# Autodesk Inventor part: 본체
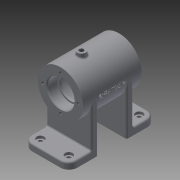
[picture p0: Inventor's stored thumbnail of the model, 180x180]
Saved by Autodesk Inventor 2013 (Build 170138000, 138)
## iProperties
Created: 2017-02
Part Number: 본체
Material: 일반
Document SubType Name: Modeling
Designer: Administrator
Density: 1 g/cm^3
Mass: 130.971 g
Surface Area: 425.852 cm^2
Volume: 130.971 cm^3
Author: Administrator
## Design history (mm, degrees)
sketch "스케치1"
  geometry: C1 r 27 at (0, 0); 1 further point
  constraints: 1 centre point, 1 coincident
  dimensions: "d0" = 54 diameter of C1
extrude "돌출1" new body sketch "스케치1" stored distance "d2" = 70; taper "d3" = 0 deg
sketch "스케치2"
  geometry: L1 (-35, 27)-(-35, -27) reference; L2 (35, -27)-(35, 27) reference; L3 (-35, 0)-(35, 0); L4 (-35, 0)-(-23, 0); L5 (-23, 0)-(-23, 16); L6 (-23, 16)-(-35, 16); L7 (-35, 16)-(-35, 0); L8 (-23, 0)-(-20, 0); L9 (-20, 0)-(-20, 14); L10 (-20, 14)-(-23, 14); L11 (-23, 14)-(-23, 0); L12 (-20, 0)-(20, 0); L13 (20, 0)-(20, 22); L14 (20, 22)-(-20, 22); L15 (-20, 22)-(-20, 0); L16 (0, 0)-(0, -10.976); L17 (20, 0)-(20, 14); L18 (23, 0)-(20, 0); L19 (20, 14)-(23, 14); L20 (23, 0)-(23, 16); L21 (23, 14)-(23, 0); L22 (35, 0)-(23, 0); L23 (35, 16)-(35, 0); L24 (23, 16)-(35, 16)
  constraints: 44 end point, 7 parallel, 5 symmetric about line, 3 horizontal, 3 perpendicular, 2 midpoint
  dimensions: "d4" = 12 distance of L5.end L6.end; "d6" = 3 distance of L9.end L10.end; "d7" = 40 distance of L13.end L14.end; "d8" = 32 diameter of L6 L4; "d9" = 28 diameter of L10 L3; "d10" = 44 diameter of L14 L3
revolve "회전1" sketch "스케치2" stored, may be unused: angle "d11" = 90 deg
node "작업 평면1"
sketch "스케치3"
  geometry: L1 (-27, -35)-(27, -35) reference; L2 (0, -35)-(0, -10); C1 r 5 at (0, -10); 1 further point
  constraints: 2 end point, 1 centre point, 1 coincident, 1 midpoint, 1 perpendicular
  dimensions: "d13" = 25 distance of L2.start L2.end; "d14" = 10 diameter of C1
extrude "돌출2" join sketch "스케치3" stored distance "d15" = 70; taper "d16" = 0 deg
hole "구멍1" diameter "d19" = 5.188; stored, may be unused: countersink angle "d23" = 90 deg, drill point angle "d25" = 118 deg; dims "d20" = 6, "d21" = 4, "d22" = 2, "d24" = 8, "d26" = 10, "d27" = 10
sketch "스케치4"
  geometry: L1 (0, 0)-(0, 21); C1 r 27 at (0, 0) reference; 1 further point
  constraints: 2 end point, 1 coincident, 1 vertical
  dimensions: "d28" = 21 distance of L1.start L1.end
hole "구멍2" sketch "스케치4" at (0, 21) diameter "d29" = 3.242; stored, may be unused: countersink angle "d33" = 90 deg, drill point angle "d35" = 118 deg; dims "d30" = 8, "d31" = 4, "d32" = 2, "d34" = 10
fillet "모깎기1" dims "d39" = 0.3, "d40" = 2
node "작업 평면3"
sketch "스케치5"
  geometry: L1 (-27, -52)-(27, -52); L2 (27, -52)-(27, -60); L3 (27, -60)-(-27, -60); L4 (-27, -60)-(-27, -52); L5 (0, -52)-(0, -60); 2 further points
  constraints: 10 end point, 3 midpoint, 2 parallel, 2 perpendicular, 1 horizontal, 1 vertical alignment
  dimensions: "d43" = 54 distance of L2.end L3.end; "d46" = 8 distance of L1.end L2.end; "d47" = 60 distance from line of L3 point (0, 0)
extrude "돌출3" join sketch "스케치5" distance "d48" = 35; taper "d49" = 0 deg
sketch "스케치6"
  geometry: L1 (54, 0)-(54, -35) reference; L2 (0, 0)-(54, 0); L3 (54, 0)-(54, -8); L4 (54, -8)-(0, -8); L5 (0, -8)-(0, 0); 1 further point
  constraints: 8 end point, 2 parallel, 1 horizontal, 1 perpendicular, 1 point on line
  dimensions: "d50" = 8 distance of L2.end L3.end
extrude "돌출4" join sketch "스케치6" stored distance "d52" = 35; taper "d53" = 0 deg
fillet "모깎기2" dims "d54" = 10
hole "구멍3" diameter "d57" = 5; stored, may be unused: countersink angle "d61" = 90 deg, drill point angle "d63" = 118 deg; dims "d55" = 10, "d56" = 10, "d58" = 8, "d59" = 9, "d60" = 3, "d62" = 10
fillet "모깎기3" dims "d67" = 2
fillet "모깎기4" dims "d68" = 2
sketch "스케치7"
  geometry: L1 (0, 0)-(16.339, -25.16); L2 (0, 0)-(0, -13.074)
  constraints: 4 end point, 1 vertical
  dimensions: "d69" = 33 deg angle of L1 L2; "d70" = 30 distance of L1.start L1.end
node "작업 평면4"
sketch "스케치8"
  geometry: C1 r 6 at (0, 0); 2 further points
  constraints: 1 centre point, 1 coincident
  dimensions: "d71" = 12 diameter of C1
extrude "돌출5" join sketch "스케치8" stored distance "d72" = 35; taper "d73" = 0 deg
hole "구멍4" diameter "d76" = 5.188; stored, may be unused: countersink angle "d80" = 90 deg, drill point angle "d82" = 118 deg; dims "d74" = 10, "d75" = 10, "d77" = 8, "d78" = 9, "d79" = 3, "d81" = 10
node "작업 평면5"
sketch "스케치9"
  geometry: L1 (0, 5.847)-(0, -5.847); L2 (-14.782, 0)-(14.782, 0); L3 (-14.782, 5.847)-(14.782, 5.847); L4 (14.782, 5.847)-(14.782, -5.847); L5 (14.782, -5.847)-(-14.782, -5.847); L6 (-14.782, -5.847)-(-14.782, 5.847); 2 further points
  constraints: 4 end point, 1 coincident, 1 midpoint, 2 other
feature "엠보싱1" sketch "스케치9" dims "d4" = 12, "d6" = 3, "d7" = 40, "d8" = 32, "d9" = 28, "d10" = 44, "d83" = 0.5, "d84" = 0
fillet "모깎기5" dims "d85" = 2
chamfer "모따기1" distance "d86" = 1; stored, may be unused: second distance "d87" = 2, angle "d88" = 45 deg
node "솔리드1"
pattern_circular "원형 패턴1" dims angle "d37" = 360 deg
mirror "대칭1"
pattern_linear "직사각형 패턴1" dims "d66" = 34
mirror "대칭2"
other parameters: "d12" = 32, "d42" = -17
